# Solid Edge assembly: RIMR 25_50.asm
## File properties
Title: Zylinder
Author: ahadarics
Template: iso metric assembly.asm
Last saved by: ahadarics
Revision: 5
Application: Solid Edge
Username: ahadarics
Dokumentum tartalom típus: 1
Document Number: RIMR 25/50
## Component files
Profilrohr.par
Kolbenstange.par
Kit_1.par
Kit_2.par
Mutter_1.par
Mutter_2.par
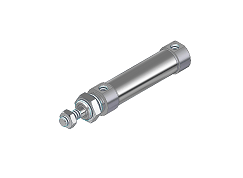
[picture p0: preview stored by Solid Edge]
